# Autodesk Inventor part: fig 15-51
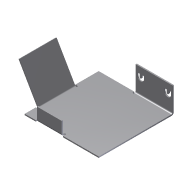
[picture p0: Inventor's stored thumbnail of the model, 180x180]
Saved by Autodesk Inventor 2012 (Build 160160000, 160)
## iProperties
Shininess: 77.0
Angle Display Precision: 2
Document Length Units: 11269
Document Angle Units: 11279
Document Time Units: 11290
Document Mass Units: 11283
Document Length Units Precision: 3
Document Angle Units Precision: 2
Created: 2002-04
Part Number: fig 15-51
Document SubType Name: Sheet Metal
Density: 1 g/cm^3
Sheet Metal Rule: Default
Material: Default
Density: 0.0
Volumn: 0.0
Area: 0.0
PropertySet Name: Model Information
Control State: 0
Master: False
Checked Out: False
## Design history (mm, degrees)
node "Face1"
  sketch "Sketch1"
    geometry: L1 (12.647, 25.882)-(12.647, -14.118); L2 (12.647, -14.118)-(-17.353, -14.118); L3 (-17.353, -14.118)-(-17.353, 15.882); L4 (-17.353, 15.882)-(-2.353, 15.882); L5 (-2.353, 15.882)-(-2.353, 25.882); L6 (-2.353, 25.882)-(12.647, 25.882); 1 further point
    constraints: 12 end point, 4 parallel, 1 perpendicular
    dimensions: "d5" = 30 distance of L2.end L3.end; "d6" = 10 distance of L4.end L5.end; "d7" = 15 distance of L3.end L4.end; "d25" = 15 distance of L5.end L1.start
sketch "Sketch3"
  geometry: L1 (10, -15)-(10, 0)
  constraints: 2 end point
feature "Fold3" sketch "Sketch3" dims "d26" = 0.5 (= BendRadius), "d27" = 90 deg, "d28" = 0.5 (= BendRadius), "d96" = 0.5 (= BendReliefWidth), "d97" = 0.25 (= BendReliefDepth), "d98" = 1 (= MinimumRemnant), "SeamGap" = 0.01, "Thickness" = 0.5
node "Flange2"
sketch "Sketch6"
  geometry: L1 (-6.914, 3.413)-(-5.843, 3.413); L2 (-5.843, 0.624)-(-6.914, 0.624); L3 (-6.914, 2.432)-(-5.843, 2.432); L4 (-5.843, 1.605)-(-6.914, 1.605); L5 (-6.914, 0.624)-(-6.914, 1.605); L6 (-6.914, 2.432)-(-6.914, 3.413); L7 (-6.914, 12.568)-(-6.914, 11.587); L8 (-6.914, 14.376)-(-6.914, 13.395); L9 (-6.914, 11.587)-(-5.843, 11.587); L10 (-5.843, 14.376)-(-6.914, 14.376); L11 (-6.914, 12.568)-(-5.843, 12.568); L12 (-5.843, 13.395)-(-6.914, 13.395); A1 r 1.394 centre (-5.843, 2.018) between (-5.843, 0.624) and (-5.843, 3.413); A2 r 0.413 centre (-5.843, 2.018) between (-5.843, 1.605) and (-5.843, 2.432); A3 r 1.394 centre (-5.843, 12.982) between (-5.843, 11.587) and (-5.843, 14.376); A4 r 0.413 centre (-5.843, 12.982) between (-5.843, 12.568) and (-5.843, 13.395)
  constraints: 24 end point, 8 point on circle, 4 centre point, 3 equal length, 1 perpendicular
cut "Cut1" sketch "Sketch6" dims "d49" = 0.5 (= Thickness), "d50" = 0
node "Flange3"
body "Solid1"
face "Plate1" dims "Thickness" = 0.5
sketch "Sketch5"
  geometry: L1 (20, 0)-(5, 0); L2 (5, 0)-(5, 15); L3 (5, 15)-(20, 15); L4 (20, 15)-(20, 0)
  constraints: 8 end point
face "Plate6" dims "d35" = 10, "d36" = 5, "d38" = 15, "d39" = 60 deg, "d40" = 0.5 (= BendRadius), "Thickness" = 0.5, "MinimumRemnant" = 1 (= 2 x Thickness), "BendReliefWidth" = 0.5 (= Thickness)
bend "Bend5" dims "d38" = 15, "d39" = 60 deg, "d40" = 0.5 (= BendRadius), "d99" = 0.5 (= BendReliefWidth), "d100" = 0.25 (= BendReliefDepth), "d101" = 1 (= MinimumRemnant), "SeamGap" = 0.01, "Thickness" = 0.5, "MinimumRemnant" = 1 (= 2 x Thickness), "BendReliefWidth" = 0.5 (= Thickness), "TransitionRadius" = 0.5 (= BendRadius)
sketch "Sketch7"
  geometry: L1 (25, 0)-(15, 0); L2 (15, 0)-(15, 5); L3 (15, 5)-(25, 5); L4 (25, 5)-(25, 0)
  constraints: 8 end point
face "Plate7" dims "d57" = 5, "d58" = 10, "d60" = 5, "d61" = 90 deg, "d62" = 0.5 (= BendRadius), "Thickness" = 0.5, "MinimumRemnant" = 1 (= 2 x Thickness), "BendReliefWidth" = 0.5 (= Thickness)
bend "Bend7" dims "d59" = 0.5 (= BendRadius), "d60" = 5, "d61" = 90 deg, "d62" = 0.5 (= BendRadius), "d102" = 0.5 (= BendReliefWidth), "d103" = 0.25 (= BendReliefDepth), "d104" = 1 (= MinimumRemnant), "SeamGap" = 0.01, "Thickness" = 0.5, "MinimumRemnant" = 1 (= 2 x Thickness), "BendReliefWidth" = 0.5 (= Thickness)
other parameters: "BendRadius" = 0.5 (= Thickness), "BendReliefDepth" = 0.25 (= 0.5 x Thickness), "CornerReliefSize" = 2 (= 4 x Thickness), "d0" = 0.5 (= BendRadius), "d13" = 0.5 (= BendRadius), "d31" = 0.5 (= BendRadius), "d37" = 0.5 (= BendRadius), "JacobiRadiusSize" = 0.5 (= Thickness), "GapSize" = 0.5 (= Thickness)
